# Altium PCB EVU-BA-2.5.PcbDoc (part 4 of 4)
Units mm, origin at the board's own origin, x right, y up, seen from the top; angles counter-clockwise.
Board outline 80 x 82.5 mm, 4 copper layers (Top Layer, Int1, Int2, Bottom Layer), stack 1.49 mm thick; 257 components, 201 nets, 889 pads, 696 vias.
Unrouted connection lines stored in the file: 1.
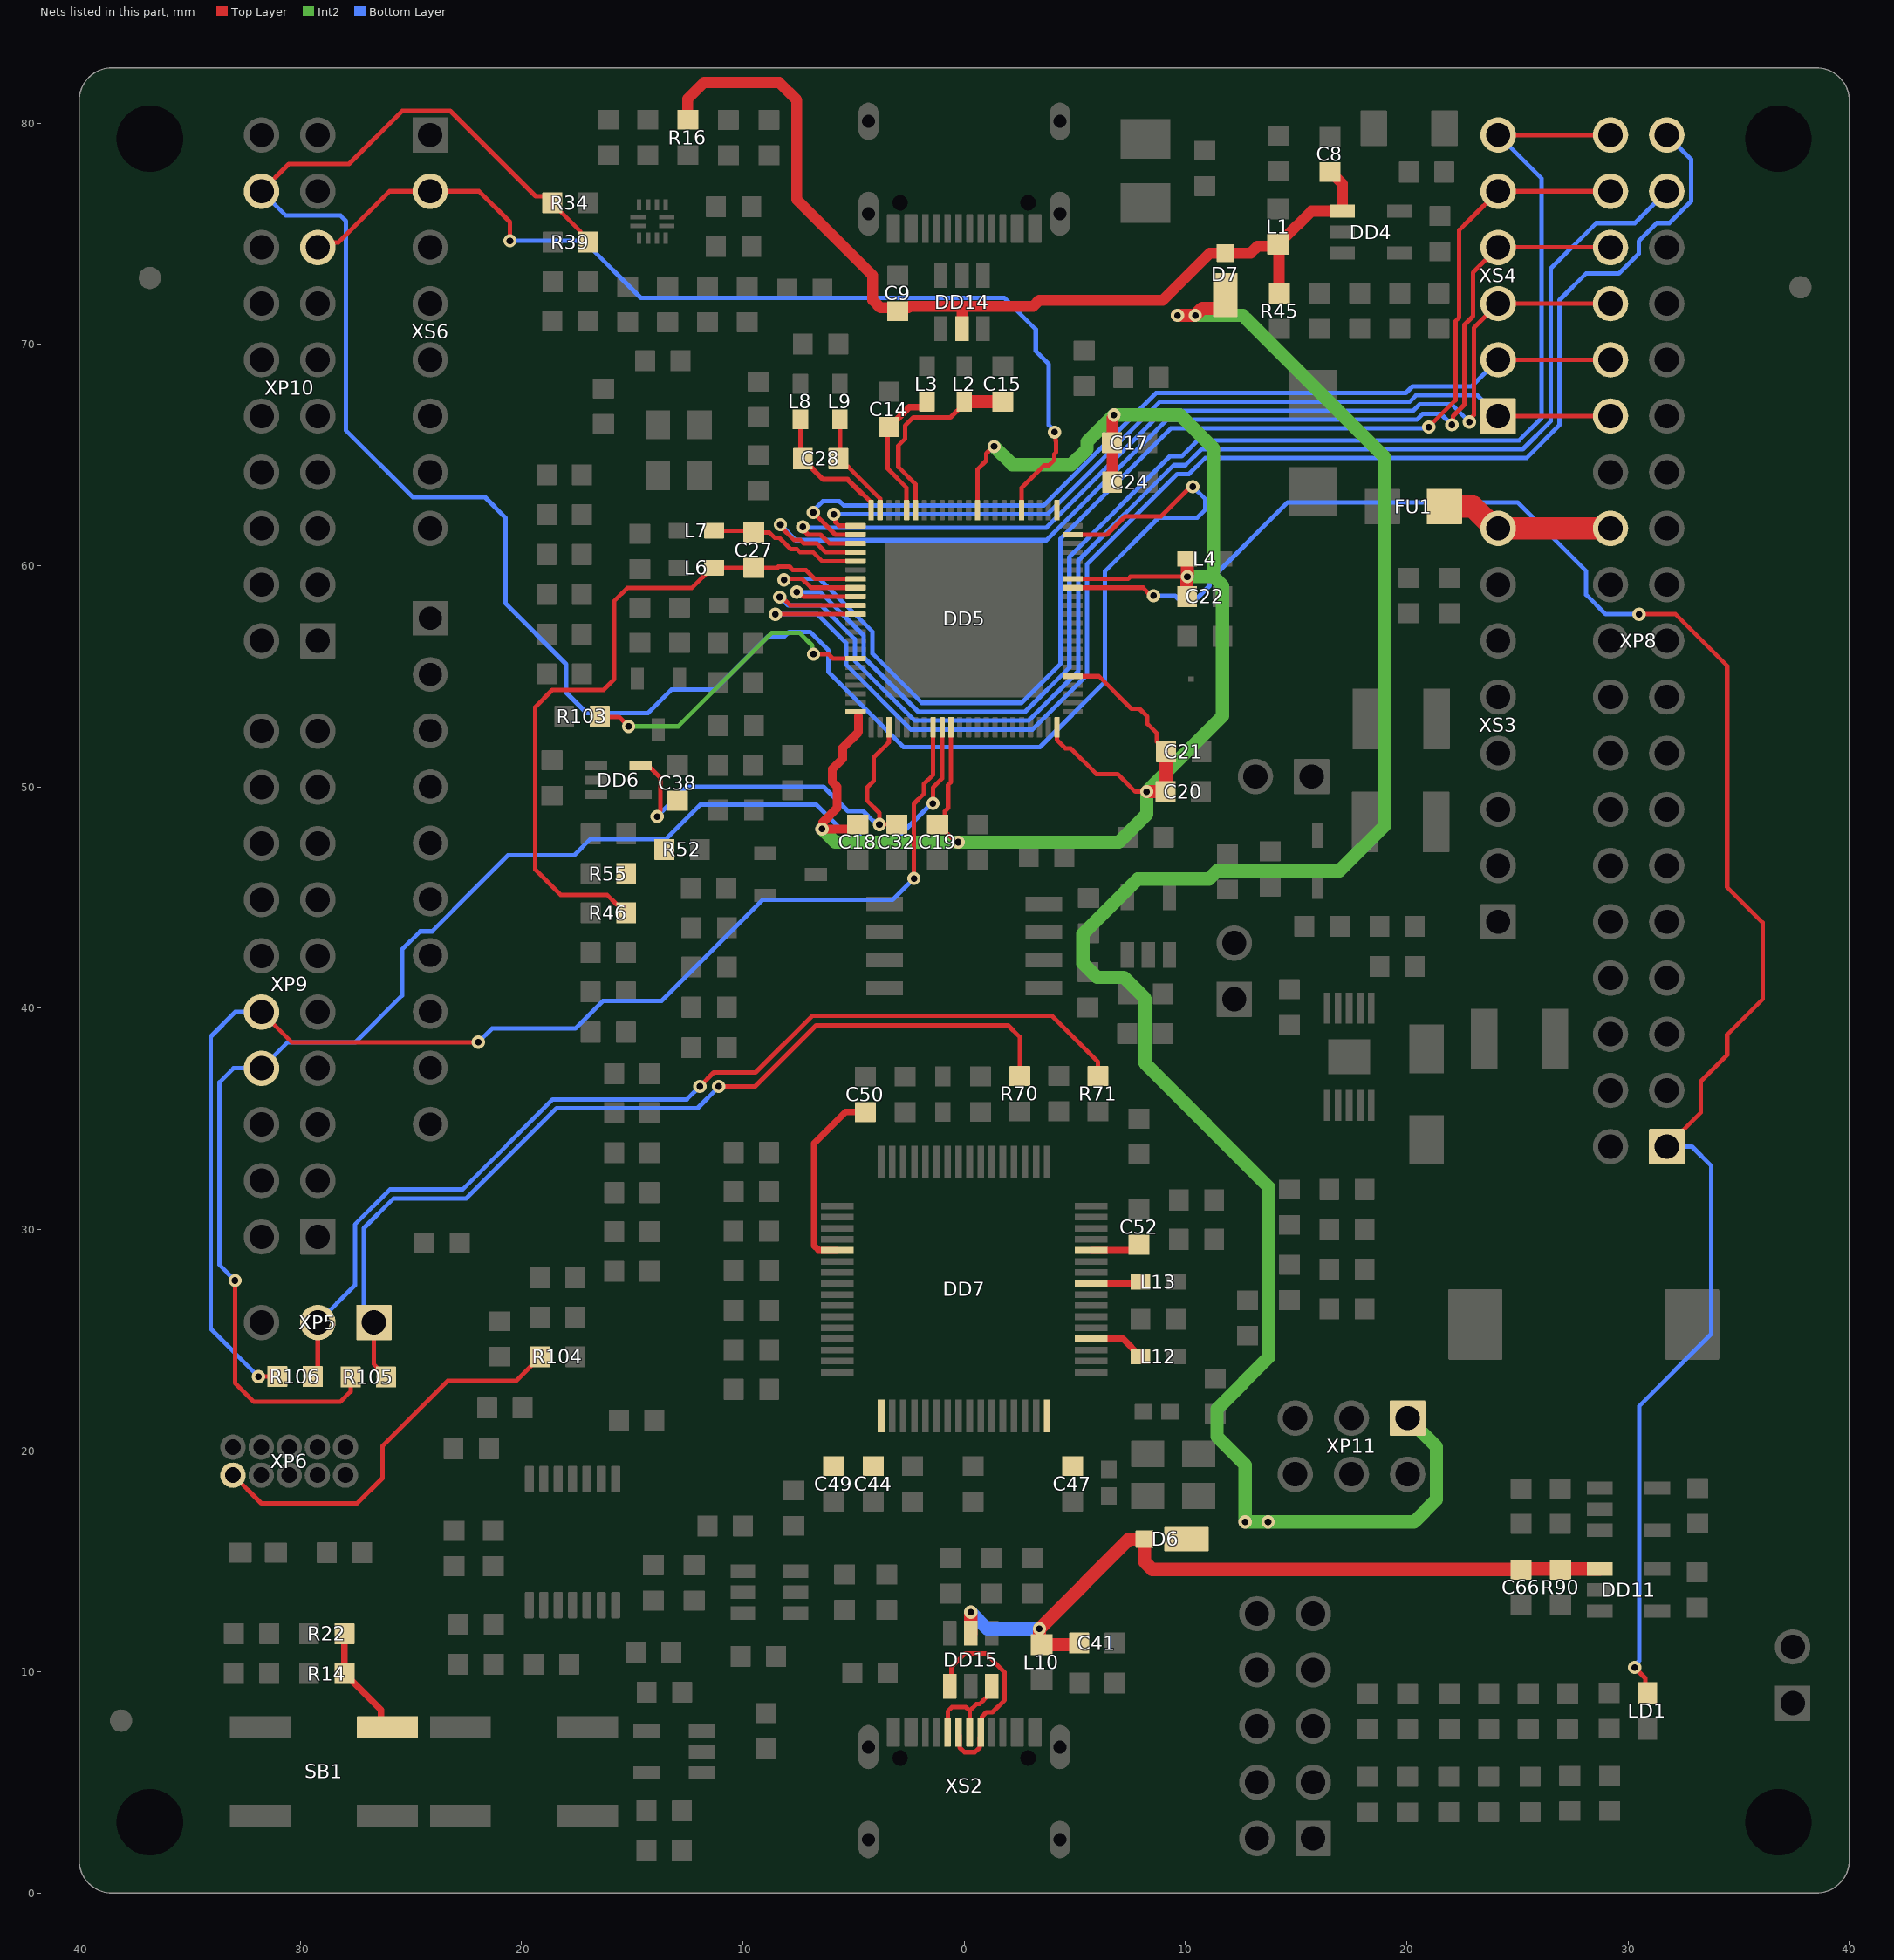
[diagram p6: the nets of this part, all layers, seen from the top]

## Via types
v1: diameter 0.6, hole 0.3, Top Layer to Bottom Layer, tented both sides, 670 vias
v2: diameter 0.6, hole 0.3, Top Layer to Bottom Layer, tented bottom, 26 vias

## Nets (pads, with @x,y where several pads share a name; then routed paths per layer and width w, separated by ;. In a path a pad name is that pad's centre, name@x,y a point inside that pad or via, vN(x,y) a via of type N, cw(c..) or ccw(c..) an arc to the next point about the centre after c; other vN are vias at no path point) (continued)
TST: DD5.38 R103.1 | length 14.1
  Top Layer w0.2: R103.1@-16.45,53.159 -15.592,53.159 v1(-15.167,52.734) ; v1(-6.807,55.999) -6.138,55.999 -5.938,55.8 DD5.38@-4.905,55.8
  Int2 w0.2: v1(-15.167,52.734) -12.922,52.734 -8.701,56.955 -7.428,56.955 -6.864,56.391 -6.864,56.056 v1(-6.807,55.999)
TUSB_INT/PB11: DD5.87 R34.2 R39.2 XP10.18 | length 99
  Top Layer w0.2: XP10.18@-31.75,76.92 -30.518,78.152 -27.798,78.152 -25.39,80.56 -23.229,80.56 -19.361,76.692 -18.909,76.692 R34.2@-18.61,76.393 -18.61,76.368 -17.347,75.105 -17.347,74.965 R39.2@-16.997,74.615 ; DD5.87@4.905,61.4 6.442,61.4 7.263,62.221 8.893,62.221 10.236,63.564 v1(10.336,63.564)
  Bottom Layer w0.2: XP10.18@-31.75,76.92 -30.65,75.82 -28.186,75.82 -27.93,75.564 -27.93,66.1 -24.918,63.087 -21.653,63.087 -20.722,62.156 -20.722,58.286 -17.979,55.543 -17.979,54.258 -17.054,53.334 -14.284,53.334 -13.223,54.395 -11.261,54.395 -8.856,56.8 -8.115,56.8 -7.915,57 -6.959,57 -6.139,56.18 -6.139,55.196 -2.738,51.795 3.42,51.795 6.355,54.73 6.355,59.731 8.79,62.166 10.534,62.166 10.9,62.532 10.9,63 v1(10.336,63.564)
TX_3/PB6: DD5.5 XP10.15 XS6.2 | length 45.9
  Top Layer w0.2: XP10.15@-29.21,74.38 -28.985,74.605 -28.279,74.605 -25.964,76.92 XS6.2@-24.13,76.92 -21.923,76.92 -20.528,75.525 v1(-20.528,74.676) ; DD5.5@2.6,62.505 2.6,63.275 2.6,63.518 3.62,64.538 3.841,64.538 4.082,64.778 4.082,65.041 4.153,65.113 4.153,65.61 4.131,65.633 4.131,65.983 v1(4.082,66.032)
  Bottom Layer w0.2: v1(-20.528,74.676) -17.19,74.676 -14.614,72.1 1.812,72.1 3.238,70.674 3.238,69.693 3.826,69.105 3.826,66.35 4.082,66.094 v1(4.082,66.032)
UART0_RX/PA7: DD5.52 R106.2 XP9.10 | length 60.2
  Top Layer w0.2: v1(-31.889,23.344) R106.2@-31.039,23.344 ; XP9.10@-31.75,39.82 -30.388,38.458 v1(-21.953,38.458) ; v1(-2.271,45.857) -2.276,45.863 -2.276,49.232 -1.809,49.699 -1.809,50.136 -1.4,50.545 -1.4,52.335 DD5.52@-1.4,52.695
  Bottom Layer w0.2: v1(-31.889,23.344) -34.05,25.505 -34.05,38.711 -32.941,39.82 XP9.10@-31.75,39.82 ; v1(-21.953,38.458) -21.328,39.083 -17.562,39.083 -16.321,40.325 -13.676,40.325 -9.112,44.89 -3.236,44.89 -2.271,45.855 v1(-2.271,45.857)
UART0_TX/PA6: DD5.53 R105.2 XP9.8 | length 64.2
  Top Layer w0.2: v1(-32.95,27.69) -32.95,23.055 -32.095,22.2 -28.198,22.2 -27.729,22.67 -27.729,23.324 R105.2@-27.725,23.328 ; v1(-1.409,49.25) -1.409,49.97 -1,50.379 DD5.53@-1,52.695
  Bottom Layer w0.2: v1(-32.95,27.69) -33.65,28.39 -33.65,36.649 -33.019,37.28 XP9.8@-31.75,37.28 -30.572,38.458 -27.507,38.458 -25.4,40.566 -25.4,42.648 -24.58,43.468 -24.045,43.468 -23.042,44.47 -23.042,44.482 -20.625,46.9 -17.629,46.9 -16.887,47.643 -13.473,47.643 -11.912,49.204 -6.685,49.204 -5.581,48.1 -5.044,48.1 -4.244,47.3 -3.416,47.3 -1.466,49.25 v1(-1.409,49.25)
UART_FTDI_RX: R71.2 R106.1 XP5.2 | length 46.7
  Top Layer w0.2: R106.1@-29.439,23.344 -29.21,23.574 XP5.2@-29.21,25.789 ; v1(-11.946,36.459) -11.319,37.087 -9.424,37.087 -6.859,39.652 3.964,39.652 6.05,37.566 R71.2@6.05,36.927
  Bottom Layer w0.2: XP5.2@-29.21,25.789 -27.53,27.469 -27.53,30.219 -25.949,31.8 -22.666,31.8 -18.591,35.875 -12.53,35.875 v1(-11.946,36.459)
UART_FTDI_TX: R70.2 R105.1 XP5.1 | length 42.6
  Top Layer w0.2: XP5.1@-26.67,25.789 -26.67,23.898 -26.125,23.353 R105.1@-26.125,23.328 ; v1(-11.096,36.459) -9.448,36.459 -6.684,39.223 1.984,39.223 2.51,38.696 R70.2@2.51,36.927
  Bottom Layer w0.2: XP5.1@-26.67,25.789 -27.13,26.249 -27.13,30.053 -25.783,31.4 -22.5,31.4 -18.425,35.475 -12.053,35.475 -11.096,36.433 v1(-11.096,36.459)
USB_5V_IN: D6.1 D7.1 XP11.1 | length 92.7
  Top Layer w0.6: v1(9.644,71.306) v1(10.444,71.306) 10.763,71.625 11.65,71.625 11.8,71.775 D7.1@11.8,72.225
  Int2 w0.2: 12.654,71.253 12.73,71.176
  Int2 w0.6: v1(9.644,71.306) 12.6,71.306 12.654,71.253 ; 12.73,71.176 18.998,64.908 18.998,48.239 16.969,46.21 11.44,46.21 11.06,45.83 7.837,45.83 5.368,43.361 5.368,42.023 6.007,41.383 7.222,41.383 8.171,40.434 8.171,37.504 13.777,31.898 13.777,24.233 11.425,21.881 11.425,20.627 12.7,19.351 v1(12.7,16.775) v1(13.734,16.775) 20.33,16.775 21.34,17.785 21.34,20.17 XP11.1@20.04,21.47
USB_N: DD15.3 XS2.A7 XS2.B7 | length 4.7
  Top Layer w0.2: XS2.B7@-0.75,7.27 -0.743,7.277 -0.743,8.22 -0.55,8.413 0.075,8.413 0.25,8.238 ; XS2.A7@0.25,7.27 0.25,8.238 ; DD15.3@1.245,9.35 1.245,9.095 0.85,8.7 0.85,8.695 0.694,8.54 0.552,8.54 0.25,8.238
USB_P: DD15.1 XS2.A6 XS2.B6 | length 9.5
  Top Layer w0.2: DD15.1@-0.595,9.395 -0.579,9.411 -0.579,10.21 0.051,10.84 0.964,10.84 1.823,9.981 1.823,8.719 1.274,8.17 1,8.17 0.8,7.97 0.8,7.225 XS2.B6@0.75,7.175 ; XS2.A6@-0.25,7.175 -0.2,7.125 -0.2,6.603 -0.2,6.58 0.01,6.37 0.49,6.37 0.7,6.58 0.7,7.025 XS2.B6@0.75,7.075
USER_BUT: R14.1 R22.1 SB1.2 | length 5.1
  Top Layer w0.3: R14.1@-28.001,9.922 R14.1@-28.001,9.897 ; R22.1@-28.001,11.722 R14.1@-28.001,9.897 ; SB1.2@-26.063,7.5 -26.353,7.79 -26.353,8.274 -27.676,9.597 -27.701,9.597 R14.1@-28.001,9.897
USER_LED/PC0: DD5.81 LD1.1 XP8.1 | length 87.5
  Top Layer w0.2: DD5.81@4.905,59 8.086,59 8.447,58.64 v1(8.555,58.64) ; v1(30.3,10.2) 30.785,9.715 30.785,9.12 LD1.1@30.872,9.033 ; v1(30.5,57.8) 32.15,57.8 34.48,55.47 34.48,45.462 36.08,43.862 36.08,40.395 34.48,38.795 34.48,37.879 33.28,36.679 33.28,35.27 XP8.1@31.75,33.74
  Bottom Layer w0.2: v1(8.555,58.64) 9.533,58.64 9.673,58.5 10.502,58.5 11.087,59.086 11.087,59.325 14.623,62.86 25.004,62.86 28.11,59.754 28.11,58.684 28.994,57.8 v1(30.5,57.8) ; v1(30.3,10.2) 30.3,10.308 30.5,10.508 30.5,22.006 33.762,25.268 33.762,30.185 33.767,30.19 33.767,32.863 32.891,33.74 XP8.1@31.75,33.74
VBUS_FTDI: C41.1 C66.2 D6.2 DD11.1 DD15.5 L10.2 R90.1 | length 35
  Top Layer w0.6: DD15.5@0.295,11.744 v1(0.295,12.7) ; L10.2@3.4,11.229 v1(3.4,11.946) 7.45,15.996 8.146,15.996 D6.2@8.15,16 8.15,14.976 8.501,14.625 C66.2@25.17,14.625 ; L10.2@3.5,11.229 5.129,11.229 C41.1@5.2,11.3 ; C66.2@25.17,14.65 26.95,14.65 DD11.1@28.725,14.65
  Bottom Layer w0.6: v1(0.295,12.7) 1.049,11.946 v1(3.4,11.946)
VBUS_MK_USB: C8.2 C9.1 D7.2 DD4.1 DD14.5 L1.2 R16.1 R45.1 | length 45.3
  Top Layer w0.5: R16.1@-12.491,80.152 -12.491,81.101 -11.756,81.836 -8.358,81.836 -7.561,81.039 -7.561,76.542 -4.131,73.112 -4.131,72.001 -3.78,71.65 -3.15,71.65 C9.1@-3,71.5 -2.85,71.65 -2.524,71.65 -2.453,71.721 -0.618,71.721 ; -0.568,71.721 3.122,71.721 3.395,71.994 8.977,71.994 11.109,74.125 D7.2@11.8,74.125 12.95,74.125 13.258,74.433 L1.2@14.108,74.433 ; DD14.5@-0.1,70.711 -0.1,71.671 ; R45.1@14.25,72.3 14.225,72.325 14.225,74.25 14.225,74.5 L1.2@14.2,74.525 14.225,74.525 14.45,74.75 14.45,74.775 15.7,76.025 DD4.1@17.082,76.025 17.082,77.259 16.556,77.785 C8.2@16.531,77.785
VCCA: C14.1 DD5.18 L3.2 | length 6.4
  Top Layer w0.2: C14.1@-3.1,66.562 C14.1@-3.4,66.262 -3.45,66.211 -3.45,64.368 -2.6,63.518 -2.6,62.865 DD5.18@-2.6,62.505 ; L3.2@-1.883,67.149 -1.683,67.349 L3.2@-1.683,67.412
  Top Layer w0.3: C14.1@-3.1,66.562 -3.075,66.562 -2.483,67.154 -1.883,67.154 L3.2@-1.883,67.149
VDD_PLL: C28.2 DD5.22 L8.2 | length 6.1
  Top Layer w0.2: L8.2@-7.4,66.612 -7.392,66.604 -7.392,64.913 C28.2@-7.289,64.81 ; -4.628,63.255 -4.6,63.255 -4.22,62.875 -4.22,62.525 DD5.22@-4.2,62.505
  Top Layer w0.24: C28.2@-7.289,64.81 -6.378,63.899 -5.272,63.899 -4.628,63.255
VDDA: C15.1 DD5.17 L2.2 | length 9.2
  Top Layer w0.2: DD5.17@-2.2,62.505 -2.2,63.582 -2.2,63.684 -2.974,64.458 -2.974,65.422 -2.675,65.721 -2.675,66.325 -2.296,66.704 -2.074,66.704 -2.069,66.699 -0.613,66.699 0,67.312 L2.2@0,67.412
  Top Layer w0.6: L2.2@0,67.412 C15.1@1.745,67.412
VDDIO: C17.1 C18.1 C19.1 C20.1 C21.1 C22.1 C24.1 DD5.1 DD5.10 DD5.44 DD5.54 DD5.66 DD5.71 DD5.82 L4.2 | length 87.9
  Top Layer w0.2: DD5.54@-0.6,52.695 -0.6,50.213 -0.725,50.088 -0.725,49.04 -0.864,48.9 -0.864,48.636 C19.1@-1.2,48.3 -1.175,48.3 -0.375,47.5 v1(-0.275,47.5) ; DD5.10@0.6,62.505 0.6,64.346 1,64.746 1,65.065 1.317,65.382 v1(1.353,65.382) ; DD5.66@4.2,52.695 4.2,52.109 4.574,51.735 4.818,51.735 5.972,50.582 6.931,50.582 7.733,49.78 v1(8.251,49.78) ; DD5.71@4.905,55 6.09,55 7.557,53.533 7.918,53.533 8.279,53.172 8.279,52.849 8.715,52.413 8.715,52.042 8.95,51.807 8.975,51.807 C21.1@9.113,51.669 ; DD5.82@4.905,59.4 7.413,59.4 7.513,59.5 v1(10.087,59.5) ; C24.1@6.686,63.745 C24.1@6.686,63.77 ; C20.1@9.101,49.78 C20.1@9.113,49.792
  Top Layer w0.4: v1(-6.423,48.093) -5.012,48.093 C18.1@-4.805,48.3 ; v1@-6.423,48.117 -6.384,48.155 -6.384,48.401 -5.741,49.044 -5.741,50.007 -5.957,50.222 -5.957,50.802 -5.495,51.263 -5.495,51.757 -4.77,52.482 -4.77,53.2
  Top Layer w0.5: C24.1@6.686,63.77 6.686,65.572 6.68,65.578 6.68,66.692 6.77,66.781 v1(6.77,66.808) ; v1@10.068,59.481 v1(10.087,59.5) v1@10.081,59.506 ; L4.2@10.075,60.3 L4.2@10.081,60.294
  Top Layer w0.6: v1(8.251,49.78) C20.1@9.101,49.78 ; C20.1@9.113,49.792 C21.1@9.113,51.669 ; C22.1@10.068,58.6 v1@10.068,59.481 ; v1@10.081,59.506 L4.2@10.081,60.294
  Int2 w0.6: v1(-6.423,48.093) -5.829,47.5 v1(-0.275,47.5) 6.993,47.5 8.251,48.757 v1(8.251,49.78) 11.675,53.204 11.675,59.088 11.262,59.5 ; v1(1.353,65.382) 2.174,64.562 4.848,64.562 5.553,65.267 5.553,65.592 v1(6.77,66.808) 9.756,66.808 11.262,65.302 11.262,59.5 ; v1(10.087,59.5) 11.262,59.5
VIN: FU1.1 XP8.24 XS3.8 | length 7.8
  Top Layer w1: FU1.1@21.802,62.66 22.995,62.66 23.975,61.68 XS3.8@24.13,61.68 XP8.24@29.21,61.68
VIN<0>: DD5.23 XP8.28 XS4.1 | length 39.1
  Top Layer w0.2: v1(-5.889,62.317) -5.813,62.241 -5.813,61.958 -5.655,61.8 DD5.23@-4.905,61.8 ; XS4.1@24.13,66.76 XP8.28@29.21,66.76
  Bottom Layer w0.2: v1(-5.889,62.317) 3.756,62.317 8.839,67.4 20.128,67.4 20.424,67.696 23.194,67.696 XS4.1@24.13,66.76
VIN<1>: DD5.24 XP8.30 XS4.2 | length 41.4
  Top Layer w0.2: v1(-6.82,62.4) -5.82,61.4 DD5.24@-4.905,61.4 ; XS4.2@24.13,69.3 XP8.30@29.21,69.3
  Bottom Layer w0.2: v1(-6.82,62.4) -6.82,62.485 -6.388,62.917 -5.641,62.917 -5.441,62.717 3.59,62.717 8.673,67.8 19.963,67.8 20.258,68.096 22.926,68.096 XS4.2@24.13,69.3
VIN<2>: DD5.25 XP8.32 XS4.3 | length 46.5
  Top Layer w0.2: v1(-7.289,61.75) -7.289,61.642 -7.08,61.433 -7.08,61.4 -6.489,61.4 -6.089,61 DD5.25@-4.905,61 ; v1(22.83,66.49) 22.83,66.598 23.03,66.798 23.03,70.74 XS4.3@24.13,71.84 XP8.32@29.21,71.84
  Bottom Layer w0.2: v1(-7.289,61.75) -7.256,61.717 3.722,61.717 9.004,67 20.294,67 20.59,67.296 22.024,67.296 v1(22.83,66.49)
VIN<3>: DD5.26 XP8.34 XS4.4 | length 51.1
  Top Layer w0.2: v1(-8.304,61.85) -8.304,61.773 -7.684,61.153 -7.399,61.153 -7.246,61 -6.655,61 -6.255,60.6 DD5.26@-4.905,60.6 ; v1(22.04,66.362) 22.09,66.412 22.09,66.76 22.6,67.27 22.6,70.876 23,71.276 23,73.25 XS4.4@24.13,74.38 XP8.34@29.21,74.38
  Bottom Layer w0.2: v1(-8.304,61.85) -7.604,61.15 3.72,61.15 9.17,66.6 20.46,66.6 20.72,66.86 21.542,66.86 v1(22.04,66.362)
VIN<4>: DD5.30 XP8.36 XS4.5 | length 61
  Top Layer w0.2: v1(-8.144,59.353) -8.097,59.4 -7.317,59.4 -6.917,59 DD5.30@-4.905,59 ; v1(20.998,66.26) 20.998,66.27 22.2,67.472 22.2,71.041 22.375,71.216 22.375,75.165 22.86,75.65 XS4.5@24.13,76.92 XP8.36@29.21,76.92
  Bottom Layer w0.2: v1(-8.144,59.353) -8.097,59.4 -6.531,59.4 -4.139,57.008 -4.139,56.025 -1.91,53.795 2.592,53.795 4.355,55.559 4.355,61.219 9.336,66.2 20.938,66.2 v1(20.998,66.26)
VIN<5>: DD5.31 XP8.38 XS4.6 | length 66.3
  Top Layer w0.2: v1(-7.566,58.8) -7.458,58.8 -7.258,58.6 DD5.31@-4.905,58.6 ; XS4.6@24.13,79.46 XP8.38@29.21,79.46
  Bottom Layer w0.2: v1(-7.566,58.8) -6.497,58.8 -4.539,56.843 -4.539,55.859 -2.075,53.395 2.757,53.395 4.755,55.393 4.755,60.394 9.301,64.94 9.835,64.94 10.478,65.583 ; 10.479,65.583 10.556,65.66 25.08,65.66 26.1,66.68 26.1,77.49 XS4.6@24.13,79.46
VIN<6>: DD5.32 XP8.35 | length 63.4
  Top Layer w0.2: v1(-8.334,58.576) -8.237,58.576 -7.861,58.2 DD5.32@-4.905,58.2
  Bottom Layer w0.2: v1(-8.334,58.576) -7.958,58.2 -6.462,58.2 -4.939,56.677 -4.939,55.694 -2.241,52.995 2.923,52.995 5.155,55.227 5.155,60.228 9.467,64.54 10.001,64.54 ; 10.002,64.54 10.722,65.26 25.246,65.26 26.5,66.514 26.5,67.08 26.5,73.418 28.562,75.48 30.31,75.48 XP8.35@31.75,76.92
VIN<7>: DD5.33 XP8.37 | length 67.6
  Top Layer w0.2: v1(-8.529,57.8) DD5.33@-4.905,57.8
  Bottom Layer w0.2: v1(-8.529,57.8) -6.628,57.8 -5.339,56.511 -5.339,55.528 -2.407,52.595 3.089,52.595 5.555,55.062 5.555,60.063 9.632,64.14 10.167,64.14 ; 10.168,64.14 10.887,64.86 25.411,64.86 26.9,66.349 26.9,66.473 26.9,72 28.095,73.195 29.581,73.195 30.48,74.094 30.48,74.666 31.294,75.48 31.866,75.48 32.85,76.464 32.85,78.36 XP8.37@31.75,79.46
VPHY: DD7.4 L12.1 | length 2.6
  Top Layer w0.3: DD7.4@5.738,25.05 7.17,25.05 L12.1@7.967,24.254
VPLL: DD7.9 L13.1 | length 2.2
  Top Layer w0.3: DD7.9@5.738,27.55 L13.1@7.933,27.55
VREF_1V: C32.2 C38.1 DD5.47 DD6.5 R52.2 R55.2 | length 20.1
  Top Layer w0.2: DD6.5@-14.625,50.95 -14.525,50.85 -14.171,50.85 -13.721,50.4 -13.721,48.92 -13.875,48.766 v1(-13.875,48.658) ; DD5.47@-3.4,52.695 -3.4,52.013 -3.43,51.983 -4.095,51.318 -4.095,50.259 -4.39,49.964 -4.39,49.379 -3.83,48.819 v1(-3.83,48.3) C32.2@-3.045,48.3
  Bottom Layer w0.2: v1(-13.875,48.658) -12.529,50.004 -6.354,50.004 -5.25,48.9 -4.564,48.9 -4.121,48.457 -4.095,48.457 -3.938,48.3 v1(-3.83,48.3)
VREFN: C27.1 DD5.27 L7.2 | length 7
  Top Layer w0.2: L7.2@-11.3,61.575 -9.575,61.575 C27.1@-9.5,61.5 -8.803,61.5 -8.553,61.25 -8.347,61.25 -7.85,60.753 -7.564,60.753 -7.411,60.6 -6.82,60.6 -6.42,60.2 DD5.27@-4.905,60.2
VREFP: C27.2 DD5.29 L6.2 R46.1 | length 31.5
  Top Layer w0.2: R46.1@-15.325,44.305 -15.325,44.33 -15.675,44.68 -15.7,44.68 -16.14,45.12 -18.24,45.12 -19.378,46.258 -19.378,53.613 -18.616,54.375 -16.298,54.375 -15.822,54.851 -15.822,58.391 -15.227,58.985 -12.315,58.985 L6.2@-11.4,59.9 ; L6.2@-11.3,59.9 C27.2@-9.5,59.9 -8.446,59.9 -8.393,59.953 -7.896,59.953 -7.743,59.8 -7.152,59.8 -6.752,59.4 DD5.29@-4.905,59.4
VREGOUT: C44.2 C47.1 C49.2 C50.1 C52.1 DD7.12 DD7.37 DD7.49 DD7.64 | length 10.9
  Top Layer w0.3: DD7.37@-5.738,29.05 -6.569,29.05 -6.776,29.257 -6.776,33.892 -5.366,35.302 C50.1@-4.465,35.302 ; DD7.12@5.738,29.05 7.65,29.05 C52.1@7.9,29.3
VSS_PLL: C28.1 DD5.21 L9.2 | length 5
  Top Layer w0.2: L9.2@-5.615,66.612 -5.615,64.909 C28.1@-5.689,64.835 -5.689,64.81 -5.339,64.46 -5.239,64.46 -3.8,63.021 DD5.21@-3.8,62.505
VTRef: R104.2 XP6.1 | length 18
  Top Layer w0.2: XP6.1@-33.039,18.888 -31.764,17.613 -27.431,17.613 -26.284,18.759 -26.284,20.206 -23.344,23.146 -20.248,23.146 -19.523,23.871 -19.521,23.871 -19.171,24.221 R104.2@-19.171,24.246
pads on no net: DD2.4 DD5.35 DD7.18 DD7.19 DD7.22 DD7.23 DD7.24 DD7.26 DD7.27 DD7.28 DD7.29 DD7.30 DD7.32 DD7.33 DD7.34 DD7.36 DD7.45 DD7.46 DD7.54 DD7.55 DD7.57 DD7.58 DD7.59 DD7.60 DD11.4 DD13.4 FM1.1 FM2.1 FM3.1 XP8.29 XP8.31 XS1. XS1.A8 XS1.B8 XS2. XS2.A8 XS2.B8 XS3.1

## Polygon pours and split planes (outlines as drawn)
VREF_1V on Top Layer "VREF_1V_L01_P010" (solid, pour order 10): -12.475,49.803 -12.475,48.262 -13.1,47.637 -13.093,47.63 -13.093,46.716 -14.209,45.6 -15.703,45.6 -15.725,45.623 -15.725,46.528 -15.703,46.55 -15.518,46.55 -14.15,47.917 -14.15,49.077 -13.425,49.803
GND on Top Layer "Top Layer-GND" (solid, pour order 83): 3.303,44.793 3.303,47.609 7.235,47.609 7.304,47.678 7.304,44.87 6.99,44.87 6.004,43.885 6.004,33.046 6.187,32.864 6.187,31.62 7.354,30.452 8.779,30.452 8.779,31.877 9.104,32.202 10.379,32.202 10.817,31.765 10.817,27.109 cw(c10.052,27.179) 9.982,26.415 9.567,26.415 9.139,26.415 9.139,25.465 11.3,25.465 11.909,26.342 13.255,26.344 13.359,26.449 13.359,36.651 13.705,36.997 33.097,36.997 33.097,20.302 39.929,20.302 39.929,82.497 -40.071,82.497 -40.071,0.002 39.092,0.002 39.929,0.908 39.929,20.302 29.674,20.302 21.2,13.833 17.734,13.833 17.742,9.944 12.629,9.944 12.629,15.177 6.773,15.177 6.773,8.413 2.829,8.413 2.829,5.434 -2.971,5.434 -2.971,8.413 -1.476,9.908 -1.476,12.37 -8.454,12.375 -8.454,9.944 -8.571,9.802 -11.08,9.802 -11.08,14.461 -12.471,15.852 -12.471,17.602 -23.122,17.602 -33.793,17.602 -33.793,48.02 -20.131,61.682 -17.6,61.682 -17.6,54.754 -20.293,54.754 -20.598,54.448 -20.598,48.678 -16.714,44.793
VREGOUT on Top Layer "Top Layer-VREGOUT" (solid, remove dead copper, pour order 14): 5.375,26.05 3.651,26.05 3.651,23.823 4.447,23.027 5.065,23.027 5.375,22.716 5.375,18.9 4.425,18.9 4.425,19.85 3.6,20.675 3.6,21.4 3.438,21.562 -3.625,21.562 -3.625,18.95 -3.675,18.9 -6.375,18.9 -6.375,22.019 -6.094,22.3 -5.697,22.3 -5.4,22.597 -5.4,29.2 5.375,29.2
GND on Top Layer "NONET_L01_P-001" (solid, remove dead copper, pour order 62): 6.954,24.921 6.947,19.096 6.601,18.75 6.125,18.75 5.375,19.5 5.375,23.027 4.447,23.027 3.651,23.823 3.651,26.05 5.826,26.05
GND on Top Layer "Top Layer-GND 1" (solid, remove dead copper, pour order 75): -34.444,47.386 -34.444,24.299 -25.67,24.299 -25.67,17.102 -10.428,17.102 -10.428,16.121 -9.9,16.121 -9.9,16.096 -8.2,16.096 -7.855,15.751 -7.855,14.4 -7,14.4 -6.7,14.1 -4.9,14.1 -4.9,15.788 -3.684,15.788 -1.058,15.751 0.875,17.272 0.875,18.1 -6.375,18.1 -6.952,19.056 -6.952,22.521 -6.681,22.521 -6.489,22.713 -6.476,22.7 -6.476,23.7 -5.001,23.7 -5,24.55 -7.213,24.55 -9.369,22.394 -16.425,29.45 -16.425,39.229 -28.396,51.2 -30.63,51.2
GND on Top Layer "NONET_L01_P-001" (solid, remove dead copper, pour order 73): -9.995,35.839 -6.384,39.45 1.068,39.45 1.975,38.543 1.975,36.38 -3.648,36.38 -3.727,36.301 -3.727,34.845 -3.704,34.822 -4.479,34.047 -4.479,32.75 3.5,32.75 5.296,30.954 5.296,29.45 -5.479,29.45 -5.479,31.45 -7.132,31.45 -7.254,31.327 -7.254,30.45 -8.182,30.45 -8.604,30.872 -8.604,32.902 -8.607,32.902 -10.132,34.427 -13.216,34.427 -13.216,35.429 -12.806,35.839
FTDI_VCCIO on Top Layer "NONET_L01_P-001" (solid, remove dead copper, pour order 40): -3.125,35.741 1.249,35.741 2.4,34.591 2.4,33.038 -3.4,33.038 -3.4,35.466
5V_INT on Top Layer "5V_INT_L01_P036" (solid, remove dead copper, pour order 36): 13.825,20.47 13.825,24.46 13.825,26.828 14.225,27.228 15.15,27.228 15.15,25.973 15.623,25.5 17.382,25.5 17.65,25.768 17.65,26.85 20.35,26.85 20.9,26.3 20.9,24.2 21.7,23.4 25.5,23.4 26.1,24 26.1,40.2 27.9,40.2 27.9,32.085 28.61,31.375 33.15,31.375 34.375,30.15 34.375,23.35 33.125,22.1 20.902,22.1 19.602,23.4 15.9,23.4 15.9,20.47
5V on Top Layer "5V_L01_P034" (solid, pour order 34): 26.7,16.758 13.917,16.758 13.917,20.2 25.8,20.2 28.477,20.2 29.3,19.377 29.3,18 28.15,18
5V on Top Layer "NONET_L01_P-001" (solid, remove dead copper, pour order 33): 21.099,77.31 21.086,77.323 21.086,80.566 23,80.566 23,77.317
3V3_QSPI on Top Layer "NONET_L01_P-001" (solid, remove dead copper, pour order 20): 3.724,46.928 3.724,44.38 5.88,44.38 6.073,44.573 6.073,46.812 5.61,47.275 4.071,47.275
3V3_FTDI on Top Layer "3V3_FTDI_L01_P024" (solid, remove dead copper, pour order 24): 30.75,16.1 30.779,16.071 33.829,16.071 34.735,15.165 34.735,14.057 32.678,14.057 32.671,14.05 32.371,14.35 30.75,14.35
NetC68_2 on Top Layer "NETC68_2_L01_P035" (solid, remove dead copper, pour order 35): 18.3,36.3 18.3,33.276 21.9,29.676 21.9,24.4 24.325,24.4 24.325,33.628 22.472,35.15 20.15,35.15 19,36.3
GND on Top Layer "GND_L01_P039" (solid, remove dead copper, pour order 39): 17.8,32.275 17.8,27.75 17.85,27.7 21,27.7 21,29.675 18.4,32.275
LDO_OUT_1P1 on Int2 "LDO_OUT_1P1_L03_P078" (solid, pour order 78): -7.044,69.389 -7.8,69.389 -7.8,55.999 -8.965,55.999 -9.045,55.919 -9.045,55.311 -8.883,55.149 -7.885,55.149 -7.376,54.64 -7.376,51.369 -3.573,47.809 7.216,47.72 11.577,53.102 11.772,64.641 7.875,68.301 1.237,68.301 1.237,69.104 1.002,69.339 0.183,69.339 -0.055,69.101 -0.055,68.565 -7.044,68.633
3V3_FTDI on Int2 "3V3_FTDI_L03_P077" (solid, remove dead copper, pour order 77): 8.473,37.202 13.777,31.898 13.777,24.203 16.51,21.47 24.68,21.47 29.884,16.266 33.684,16.266 34.9,15.05 34.9,14.1 34.4,13.6 14.9,13.6 10.35,13.486 -7.111,13.486 -14.85,21.225 -14.85,24.095 -1.564,37.632 -1.573,38.101 -1.256,38.425 -0.445,38.425 7.25,38.425
3V3 on Int2 "3V3_L03_P079" (solid, pour order 79): -40,82.5 -40,0 40,0 40,82.5
GND on Bottom Layer "Bottom Layer-GND" (solid, remove dead copper, pour order 74): 7.883,49.959 7.883,50.079 6.779,51.182 5.913,51.182 5.913,48.633 5.098,47.818 -4.676,47.818 -5.877,49.019 -12.187,49.019 -13.837,47.369 -21.932,47.369 -24.312,44.989 -24.312,60.448 -23.286,61.473 -20.43,58.617 -18.341,56.528 -18.341,54.531 -17.179,53.369 -14.975,53.369 -13.481,54.864 -11.439,54.864 -8.541,57.761 -8.541,58.001 -12.112,58.001 -12.112,59.969 -9.312,62.769 -9.312,66.919 -8.793,67.438 3.876,67.438 2.7,67.438 2.7,82.569 -40.012,82.569 -40.012,0.069 39.988,0.069 39.988,82.569 -8.012,82.569 2.7,82.569 2.7,67.448 19.389,67.308 20.246,68.165 22.914,68.165 24.118,69.369 24.118,79.529 31.738,79.529 31.738,57.869 28.538,57.869 25.949,60.458 22.971,60.478 20.94,62.944 14.62,62.944 10.904,59.228 10.863,55.409 27.148,55.409 30.401,55.409 31.738,54.072 31.738,43.051 31.126,42.439 28.849,42.439 28.047,41.637 28.047,41.429 27.044,40.427 21.854,40.427 17.539,44.989 17.539,48.733 16.314,49.959
GND on Bottom Layer "GND_L04_P086" (solid, pour order 86): -23.407,51.088 -23.407,48.314 -23.193,48.1 -18.126,48.1 -17.104,49.123 -17.178,49.197 -17.178,49.523 -21.843,49.523
GND on Bottom Layer "GND_L04_P084" (solid, pour order 84): -21.39,51.65 -16.088,51.65 -15,50.562 -15.475,50.087 -15.475,49.923 -21.513,49.923 -23.573,51.983 -22.915,51.325 -22.915,53.144 -21.68,51.909
3V3 on Bottom Layer "NONET_L01_P-001" (solid, remove dead copper, pour order 57): -12.1,57.931 -9.061,57.931 -9.029,57.899 -8.991,57.938 -8.991,60.391 -7.496,60.391 -5.531,62.356 3.888,62.356 7.325,65.792 7.325,66.451 6.455,66.451 4.999,64.995 -0.094,64.995 -1.651,63.438 -2.519,63.438 -2.882,63.8 -8.2,63.8 -12.1,59.9
GND on Bottom Layer "NONET_L01_P-001" (solid, remove dead copper, pour order 56): 4.386,61.156 -7.687,61.156 -7.838,61.006 -7.838,59.4 -6.531,59.4 -4.139,57.008 -4.139,55.721 -2.213,53.795 2.592,53.795 4.353,55.557 4.353,55.563
GND on Int1 "GND_L02_P000" (solid, pour order 0): -40.199,82.404 -40.199,-0.096 39.801,-0.096 39.801,82.404

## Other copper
Top Layer:
  pour cut-out: -5.131,36.452 -5.131,35.741 2.96,35.741 2.96,36.452
  pour cut-out: -17.407,77.164 -21.925,77.164 -21.925,74.437 -21.939,74.423 -17.749,70.233 -13.949,70.233 -13.949,68.68 -17.178,68.68 -17.178,65.593 -13.403,65.593 -13.403,63.243 -11.039,63.243 -10.403,63.942 -10.411,65.261 -10.778,65.628 -10.778,67.243 -8.836,67.243 -8.836,63.374 -9.517,62.418 -11.557,62.418 -12.027,61.948 -12.027,57.632 -10.366,57.632 -10.31,48.118 -8.31,47.443 -8.31,48.644 -8.31,50.298 -7.08,50.298 -6.709,49.927 -6.709,47.634 -6.465,47.634 -6.287,47.443 1.669,47.443 1.669,47.559 1.873,47.763 9.902,47.763 10.496,47.763 10.496,55.618 11.245,56.368 11.245,59.775 12.688,59.79 12.688,63.078 14.494,63.103 14.494,58.692 18.81,54.377 18.81,49.427 18.81,47.1 18.259,46.549 11.464,46.549 11.183,46.269 11.183,39.678 12.223,38.638 19.467,38.638 20.202,39.373 20.202,40.12 21.12,41.038 21.12,42.84 20.861,43.1 20.125,43.1 19.915,43.31 19.915,44.19 20.088,44.363 23.428,44.363 23.519,44.454 23.583,53.1 23.531,59.983 30.008,59.983 30.882,60.858 30.882,62.588 29.274,64.196 12.597,64.196 12.597,69.649 24.181,69.649 24.069,76.963 19.7,76.963 18.81,76.073 18.81,75.563 18.569,75.322 18.569,74.788 17.309,74.788 17.309,78.696 16.964,79.04 11.898,79.04 11.344,78.486 6.686,78.486 5.801,77.601 5.801,71.078 9.362,71.078 10.997,69.443 10.997,63.422 7.864,63.422 7.839,63.397 7.828,63.408 7.828,66.049 7.962,66.049 8.364,66.45 8.364,69.418 5.892,69.418 5.801,69.327 4.319,69.327 3.596,68.604 1.462,68.604 1.152,68.915 1.152,71.743 2.302,71.743 2.302,76.963 -2.829,76.963 -3.303,76.489 -3.303,75.538 -3.172,75.538 -2.339,74.704 -2.339,72.343 -4.528,72.343 -4.528,67.804 -5.783,67.804 -6.135,68.157 -6.135,70.548 -6.267,70.68 -6.338,73.143 -10.418,73.143 -10.418,81.438 -15.267,81.438 -15.267,79.89 -17.407,79.89
  pour cut-out: -25.117,60.412 -24.229,60.412 -24.229,58.329 -26.46,58.329
  pour cut-out: 27.297,46.629 28.184,46.629 28.184,46.126 28.13,46.072 27.297,46.072
  pour cut-out: 14.494,66.508 14.688,66.508 17.044,66.508 17.044,64.196 14.494,64.196
  pour cut-out: -13.263,54.281 -13.263,52.379 -12.371,51.984 -12.371,54.33 -13.214,54.33
  pour cut-out: -14.596,12.62 -14.596,11.353 -11.725,11.353 -11.725,12.62
  pour cut-out: -18.383,10.375 -18.383,8 -14.846,8 -14.846,10.375
  pour cut-out: -33.642,12.175 -33.642,8 -27.273,8 -27.273,12.175
  pour cut-out: -32.56,12.378 -32.56,11.656 -29.023,11.656 -29.023,12.378
  pour cut-out: -10.614,23.153 -10.614,22.12 -5.553,22.12 -5.221,23.153
  pour cut-out: 20.951,16.675 20.951,15.216 24.702,15.216 24.702,16.675
  pour cut-out: 24.545,15.262 24.545,13.466 27.896,13.466 27.896,15.262
  pour cut-out: 24.491,17.84 24.491,17.118 27.896,17.118 27.896,17.84
  pour cut-out: 6.214,34.554 6.214,34.058 13.359,34.058 13.359,34.554
  pour cut-out: -11.813,34.378 -11.813,33.882 -6.776,33.882 -6.776,34.378
  pour cut-out: -12.45,8.212 -13.348,8.212 -13.348,4.396 -12.45,4.396
  pour cut-out: -21.697,12.827 -23.59,12.827 -23.59,9.722 -21.697,9.722
  pour cut-out: -15.425,15.355 -14.521,17.602 -19.797,16.416 -20.643,14.767
  region net 3V3_FTDI: 9.117,24.765 9.117,23.904 10.206,22.815 12.053,22.815 13.274,24.036 13.274,25.642 12.347,25.642 11.47,24.765
  pour cut-out: -10.19,77.886 -10.19,81.321 -10.298,81.429 -10.29,81.438 -7.96,81.438 -7.96,78.995 -8.371,77.886
  pour cut-out: -15.706,61.008 -12.238,61.008 -12.027,60.796 -12.027,60.656 -12.45,60.233 -12.48,60.263 -15.706,60.263
  pour cut-out: -16.822,64.553 -16.822,59.85 -15.996,59.85 -15.706,60.14 -15.706,64.279 -15.974,64.548
  pour cut-out: -15.803,52.525 -13.597,52.525 -12.497,51.425
  region net GND: 9.849,17.738 9.849,17.96 9.849,18.55 11.872,18.55 12.221,18.201 12.221,17.094 12.08,16.977 9.849,16.977 9.849,17.359
  pour cut-out: -19.072,50.518 -19.078,50.513 -19.078,50.05 -18.172,50.05 -18.341,50.219 -18.341,50.4
  region net 3V3: -17.375,52.102 -18.625,52.102 -19.078,51.649 -19.078,50.751 -18.499,50.75 -17.853,50.102 -17.853,49.704 -17.598,49.45 -16.125,49.45 -16.125,49.85 -17.245,49.85 -17.375,49.98 -17.375,51.725
  pour cut-out: 31.437,9.679 31.218,9.859 16.944,9.859 16.944,2.809 30.14,2.809 31.437,4.107
  pour cut-out: -3.875,9.319 -3.875,10.41 -4.022,10.557 -4.491,10.557 -4.675,10.373 -4.675,9.319
  pour cut-out: -7.345,15.788 -7.345,15.292 -2.011,15.292 -2.011,15.788
  pour cut-out: -13.205,2.562 -13.701,2.562 -13.701,1.312 -13.205,1.312
  pour cut-out: -12.13,2.412 -12.13,2.908 -13.38,2.908 -13.38,2.412
  pour cut-out: -8.33,6.987 -8.33,7.687 -9.58,7.687 -9.58,6.987
  pour cut-out: -20.051,10.822 -20.051,12.827 -21.876,12.827 -21.876,10.822
  pour cut-out: -27.651,16.012 -28.147,16.012 -28.147,14.762 -27.651,14.762
  pour cut-out: -18.23,27.353 -16.976,27.353 -16.976,26.651 -18.23,26.651
  pour cut-out: 7.879,41.83 7.882,41.827 8.769,41.827 8.769,41.325 8.715,41.27 7.879,41.27
  pour cut-out: -13.403,50.525 -13.403,49.825 -12.497,49.825 -12.524,49.852 -12.524,50.574 -13.353,50.574
  region net VDDIO: -5.112,53.4 -4.527,53.4 -4.527,52.447 -5.112,51.863
  region net VDDIO: 4.2,62.935 4.2,62.2 5.995,62.2 7.136,63.341 7.136,64.222 7.114,64.245 6.259,64.245 6.252,64.238 4.949,62.935
  region net USB_5V_IN: 9.077,16.55 12.013,16.55 12.557,17.094 13.926,17.094 14.16,16.86 14.16,16.444 13.166,15.45 9.077,15.45 9.05,15.478 9.058,15.486 9.058,16.542
  region net 3V3: 30.75,18.75 32.697,18.75 34.435,18.75 34.585,18.6 34.735,18.449 34.735,17.291 34.494,17.05 34.188,17.05 34.025,17.213 34.025,17.519 33.694,17.85 32.697,17.85 30.75,17.85
  region net GND: 9.67,22.12 12.353,22.12 12.422,22.05 12.638,21.835 12.638,21.368 12.42,21.15 10.182,21.15 8.898,21.4 8.898,22.12
  region net 3V3_FTDI: 9.1,31.628 9.1,28.908 9.1,27.2 10.128,27.2 10.128,29.075 10.15,29.098 10.15,31.778 10.128,31.8 9.272,31.8
  region net 5V: 6.048,41.176 6.702,41.83 7.675,41.83 7.675,42.98 6.525,42.98 5.622,42.076 5.143,42.076 5.121,42.054 5.121,41.199 5.143,41.176
  region net 3V3: -18.147,75.068 -18.169,75.09 -19.024,75.09 -19.047,75.068 -19.046,75.066 -19.046,72.377 -19.023,72.355 -18.168,72.355 -18.146,72.377 -18.147,72.379
  region net 3V3: -22.007,22.371 -22.007,16.204 -21.734,15.932 -20.761,15.932 -19.461,17.231 -19.461,19.252 -19.447,19.267 -20.75,20.57 -20.75,22.028 -21.122,22.4 -21.978,22.4
  region net 3V3: -13.586,75.052 -13.586,74.111 -11.625,72.15 -11.125,72.15 -11.125,73.05 -11.285,73.05 -13.286,75.052
  region net 3V3: -16.839,68.45 -16.839,67.481 -13.222,67.481 -12.5,66.759 -12.5,65.71 -11.4,65.71 -11.4,68.018 -12.372,68.99 -12.372,70.874 -12.925,71.428 -13.875,71.428 -13.875,70.573 -13.265,69.963 -13.265,68.45
  region net 3V3: -14.992,6.493 -14.992,1.5 -14.777,1.285 -13.956,1.285 -13.75,1.491 -13.75,1.553 -13.75,4.135 -13.75,6.506 -14.04,6.796 -14.69,6.796
  pour cut-out: -8.069,16.9 -7.038,16.9 -7.038,17.523 -7.265,17.75 -8.065,17.75 -8.325,17.49 -8.325,17.156
  pour cut-out: -21.658,24.796 -20.132,24.796 -20.132,25.396 -21.658,25.396
  pour cut-out: -16.067,13.602 -16.067,11.576 -19.832,11.576 -19.832,13.602
  pour cut-out: -15.547,19.997 -15.547,18.167 -19.847,18.112 -19.847,19.997
  pour cut-out: -15.225,50.625 -15.225,49.95 -13.75,49.95 -13.75,50.525 -13.85,50.625
  pour cut-out: -16.25,48.375 -16.25,47.47 -16.477,47.243 -18.941,47.243 -18.941,46.802 -16.477,46.802 -16.25,46.575 -16.25,45.67 -15.959,45.67 -15.959,46.575 -15.732,46.802 -15.026,46.802 -14.877,46.952 -14.877,47.099 -15.021,47.243 -15.732,47.243 -15.959,47.47 -15.959,48.37
  pour cut-out: -18.217,64.553 -18.217,63.648 -18.444,63.421 -19.299,63.421 -19.299,62.979 -18.444,62.979 -18.217,62.753 -18.217,61.848 -17.926,61.848 -17.926,62.753 -17.699,62.979 -16.844,62.979 -16.844,63.421 -17.699,63.421 -17.926,63.648 -17.926,64.548
  pour cut-out: -31.845,74.285 -31.804,74.326 -31.845,74.367
Int2:
  pour cut-out: 7.89,45.443 11.43,45.443 9.019,42.905 5.69,42.905
  pour cut-out: 14.574,22.1 20.04,22.1 20.04,18.93 14.574,18.93
  pour cut-out: 12.7,18.93 20.04,18.93 20.088,18.978 21.34,18.978 21.34,17.785 20.33,16.775 13.108,16.775 12.7,17.183
Bottom Layer:
  pour cut-out: -3.543,77.424 -0.199,77.424 -0.199,75.361 -1.36,74.2 -3.515,74.2

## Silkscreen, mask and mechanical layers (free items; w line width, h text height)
Top Overlay:
  drawing of 55 lines, arcs and shapes, not listed
  text "VIN7" at 31.028,81.209 h1.5
  text "GND" at -33.143,81.135 h1.5
  text "VIN5" at 25.472,79.471 h1.5 r315
  text "PB3" at -27.041,78.871 h1.5 r45
  text "VIN6" at 33.412,76.951 h1.5 r315
  text "VIN4" at 25.461,76.92 h1.5 r315
  text "MCU" at -5.101,76.479 h2.5 r90
  text "USB" at 6.407,76.479 h2.5 r90
  text "PB7" at -27.033,76.325 h1.5 r45
  text "PB11" at -34.858,75.093 h1.5 r45
  text "GND" at 33.418,74.441 h1.5 r315
  text "VIN3" at 25.472,74.391 h1.5 r315
  text "PB6" at -27.044,73.791 h1.5 r45
  text "PB10" at -34.991,72.564 h1.5 r45
  text "NC" at 33.412,71.871 h1.5 r315
  text "VIN2" at 25.461,71.84 h1.5 r315
  text "PB8" at -27.044,71.251 h1.5 r45
  text "PB9" at -34.509,70.024 h1.5 r45
  text "NC" at 33.412,69.331 h1.5 r315
  text "VIN1" at 25.461,69.3 h1.5 r315
  text "PB15" at -27.376,68.711 h1.5 r45
  text "GND" at -34.773,67.432 h1.5 r45
  text "GND" at 33.418,66.821 h1.5 r315
  text "VIN0" at 25.472,66.771 h1.5 r315
  text "PB14" at -27.375,66.16 h1.5 r45
  text "3V3" at -34.466,64.872 h1.5 r45
  text "PC15" at 33.412,64.251 h1.5 r315
  text "RST_ALL" at 23.02,63.747 h1.5
  text "PB13" at -27.376,63.631 h1.5 r45
  text "PB5" at -34.488,62.404 h1.5 r45
  text "VIN" at 25.504,61.784 h1.5 r315
  text "PC14" at 33.412,61.711 h1.5 r315
  text "PB12" at -27.365,61.08 h1.5 r45
  text "PB4" at -34.511,59.853 h1.5 r45
  text "GND" at 25.478,59.181 h1.5 r315
  text "PC13" at 33.412,59.171 h1.5 r315
  text "PB2" at -27.058,58.54 h1.5 r45
  text "GND" at -34.773,57.272 h1.5 r45
  text "GND" at 33.418,56.661 h1.5 r315
  text "GND" at 25.478,56.641 h1.5 r315
  text "PB0" at -27.044,56.011 h1.5 r45
  text "PB1" at -34.702,54.773 h1.5 r45
  text "5V" at 25.634,54.143 h1.5 r315
  text "PC12" at 33.412,54.091 h1.5 r315
  text "PA13" at -27.082,51.831 h1.5 r45
  text "3V3" at 25.486,51.581 h1.5 r315
  text "PC11" at 33.412,51.551 h1.5 r315
  text "GND" at -35.013,50.779 h1.5 r45
  text "PA8" at -27.044,49.291 h1.5 r45
  text "PC10" at 33.412,49.011 h1.5 r315
  text "RSTU" at 25.472,48.991 h1.5 r315
  text "PA12" at -35.235,48.28 h1.5 r45
  text "PA10" at -27.111,46.751 h1.5 r45
  text "3V3" at 25.486,46.501 h1.5 r315
  text "PC9" at 33.412,46.471 h1.5 r315
  text "PA15" at -35.242,45.751 h1.5 r45
  text "PA11" at -27.08,44.2 h1.5 r45
  text "PC7" at 33.412,43.931 h1.5 r315
  text "PC8" at 25.472,43.911 h1.5 r315
  text "PA14" at -35.266,43.2 h1.5 r45
  text "GND" at 25.717,41.833 h1.5 r315
  text "PA9" at -27.044,41.671 h1.5 r45
  text "PC6" at 33.412,41.391 h1.5 r315
  text "GND" at -35.013,40.619 h1.5 r45
  text "GND" at -27.054,39.067 h1.5 r45
  text "PC4" at 33.412,38.851 h1.5 r315
  text "PA7" at -34.762,38.12 h1.5 r45
  text "AREF" at -27.081,36.548 h1.5 r45
  text "PC2" at 33.412,36.311 h1.5 r315
  text "PC5" at 24.665,35.687 h1.5
  text "PA6" at -34.787,35.591 h1.5 r45
  text "PC3" at 24.665,34.292 h1.5
  text "PA5" at -27.044,34.051 h1.5 r45
  text "PC0" at 33.412,33.771 h1.5 r315
  text "PA3" at -34.756,33.051 h1.5 r45
  text "PC1" at 24.665,32.901 h1.5
  text "PA4" at -27.033,31.5 h1.5 r45
  text "PA2" at -34.754,30.5 h1.5 r45
  text "PA0" at -27.03,28.971 h1.5 r45
  text "PA1" at -34.725,27.96 h1.5 r45
  text "UART0" at -22.671,21.1 h3 r90
  text "VIN" at 12.948,16.319 h1.8
  text "EXT5V" at 15.675,16.331 h1.8
  text "USB" at 19.955,16.331 h1.8
  text "JTAG" at -24.515,15.872 h3 r90
  text "PWR SEL" at 13.3,14.325 h3
  text "GND" at 38.343,12.785 h3 r90
  text "PWR" at -33.996,12.747 h3
  text "M0" at 8.388,11.83 h3
  text "M1" at 8.438,9.29 h3
  text "M2" at 8.422,6.75 h3
  text "USER" at 33.925,5.224 h3 r90
  text "DBG" at 7.4,4.3 h3
  text "CLK" at 8,1.7 h3
  text "JTAG" at -7.55,0.448 h3 r90
  text "UART0" at -5.512,0.35 h3 r90
  text "USER" at -31.525,0.303 h3
  text "RESET" at -22.825,0.303 h3
Bottom Overlay:
  drawing of 1109 lines, arcs and shapes, not listed
  text "VIN7" at 33.025,81 h1.5
  text "GND" at -30.5,80.936 h1.5
  text "VIN5" at 22.95,79.191 h1.5
  text "PB3" at -26.226,78.976 h1.5
  text "RX/PB7" at -19.221,78.967 h1.5
  text "PB11" at -32.756,77.127 h1.5 r45
  text "VIN4" at 22.95,76.476 h1.5
  text "PB7" at -26.222,76.444 h1.5
  text "TX/PB6" at -19.215,76.41 h1.5
  text "VIN6" at 34.521,75.425 h1.5 r315
  text "VIN3" at 22.95,74.091 h1.5
  text "PB10" at -33.053,74.053 h1.5
  text "PB6" at -26.21,73.926 h1.5
  text "PB8" at -20.901,73.944 h1.5
  text "GND" at 35.228,73.813 h1.5
  text "ADC" at 19.427,71.975 h1.5 r270
  text "PB9" at -32.975,71.499 h1.5
  text "PB8" at -26.21,71.399 h1.5
  text "VIN2" at 22.95,71.376 h1.5
  text "NC" at 34.297,71.285 h1.5
  text "PWM/PB15" at -17.331,71.222 h1.5
  text "GND" at -32.975,68.957 h1.5
  text "PB14" at -20.17,68.895 h1.5
  text "PB15" at -25.606,68.872 h1.5
  text "VIN1" at 22.95,68.876 h1.5
  text "NC" at 34.297,68.745 h1.5
  text "3V3" at -32.975,66.412 h1.5
  text "PB14" at -25.575,66.34 h1.5
  text "PWM/PB13" at -17.243,66.335 h1.5
  text "VIN0" at 22.95,66.291 h1.5
  text "GND" at 35.228,66.2 h1.5
  text "PB5" at -32.975,63.847 h1.5
  text "RST_ALL" at 28.225,63.859 h1.5
  text "PB13" at -25.603,63.823 h1.5
  text "МИКРОКОНТРОЛЛЕР BE-U1000 / ОТЛАДОЧНАЯ ПЛАТА BASE / РАЗРАБОТАНО В РОССИИ" at 11.395,63.71 h2
  text "PWM/PB12" at -17.156,63.701 h1.5
  text "PC15" at 35.36,63.669 h1.5
  text "VIN" at 23.318,61.3 h1.5
  text "PB12" at -25.599,61.291 h1.5
  text "PB2" at -20.726,61.286 h1.5
  text "PB4" at -32.975,61.183 h1.5
  text "PC14" at 35.392,61.131 h1.5
  text "PB2" at -26.222,58.769 h1.5
  text "GND" at 22.95,58.768 h1.5
  text "GND" at -32.975,58.736 h1.5
  text "PC13" at 35.364,58.588 h1.5
  text "PA13" at -20.1,57.247 h1.5
  text "PB0" at -26.206,56.252 h1.5
  text "GND" at 22.95,56.222 h1.5
  text "PB1" at -32.975,56.151 h1.5
  text "GND" at 35.228,56.044 h1.5
  text "POWER" at 19.209,54.867 h1.5 r270
  text "PWM/PA12" at -17.182,54.751 h1.5
  text "5V" at 22.95,53.685 h1.5
  text "PC12" at 35.368,53.516 h1.5
  text "GND" at -32.941,52.052 h1.5
  text "PA13" at -25.525,52.067 h1.5
  text "PWM/CS/PA8" at -16.04,51.955 h1.5
  text "3V3" at 22.95,51.138 h1.5
  text "PC11" at 35.36,50.976 h1.5
  text "PWM/MOSI/ PA10" at -13.724,49.549 h1.5
  text "PA12" at -32.941,49.531 h1.5
  text "PA8" at -26.132,49.528 h1.5
  text "RST_U" at 22.86,48.559 h1.5
  text "PC10" at 35.383,48.433 h1.5
  text "PA15" at -32.941,46.991 h1.5
  text "PA10" at -25.505,46.989 h1.5
  text "MISO/PA11" at -17.032,46.993 h1.5
  text "IOREF" at 22.95,46.077 h1.5
  text "3V3" at 28.225,46.027 h1.5
  text "PC9" at 34.747,45.895 h1.5
  text "PA14" at -32.941,44.459 h1.5
  text "PA11" at -25.528,44.46 h1.5
  text "SCK/PA9" at -18.032,44.467 h1.5
  text "NC" at 22.95,43.54 h1.5
  text "PC8" at 28.225,43.507 h1.5
  text "PC7" at 34.745,43.355 h1.5
  text "PA9" at -26.128,41.927 h1.5
  text "GND" at -32.941,41.909 h1.5
  text "GND" at -20.429,41.893 h1.5
  text "GND" at 28.225,40.968 h1.5
  text "PC6" at 34.756,40.812 h1.5
  text "PA7" at -32.941,39.388 h1.5
  text "GND" at -25.754,39.377 h1.5
  text "AREF" at -20.033,39.392 h1.5
  text "BootModes: (XP1)" at 10.938,39.061 h3
  text "PC5" at 28.225,38.273 h1.5
  text "PC4" at 34.769,38.273 h1.5
  text "AREF" at -25.148,36.881 h1.5
  text "PA6" at -32.941,36.849 h1.5
  text "SDA/PA5" at -18.2,36.815 h1.5
  text "PC3" at 28.225,35.906 h1.5
  text "PC2" at 34.761,35.906 h1.5
  text "DBG" at -12.414,34.662 h2.54 r270
  text "M2" at -10.599,34.662 h2.5 r270
  text "M1" at -8.772,34.662 h2.5 r270
  text "M0" at -6.831,34.662 h2.5 r270
  text "DBG" at 3.54,34.562 h2.54 r270
  text "M2" at 5.355,34.562 h2.5 r270
  text "M1" at 7.182,34.562 h2.5 r270
  text "M0" at 9.123,34.562 h2.5 r270
  text "PA5" at -25.951,34.322 h1.5
  text "SCL/PA4" at -18.405,34.331 h1.5
  text "PA3" at -32.941,34.306 h1.5
  text "PC1" at 28.225,33.19 h1.5
  text "PC0" at 34.761,33.19 h1.5
  text "JTAG EXT" at -13.125,31.966 h2.54
  text "EFLASH" at 2.945,31.959 h2.54
  text "PA4" at -25.89,31.793 h1.5
  text "PA2" at -32.941,31.774 h1.5
  text "PA1" at -32.95,29.244 h1.5
  text "PA0" at -25.875,29.215 h1.5
  text "UART" at 2.932,27.607 h2.54
  text "PYTH UART" at -13.125,27.288 h2.54
  text "Ext 10-48V from XP8-24" at 14.273,23.665 h2.54 r270
  text "Ext 5V from XP8-18" at 16.873,23.5 h2.54 r270
  text "5V from any USB TYPE-C" at 19.544,23.5 h2.54 r270
  text "QSPI" at 2.879,23.209 h2.54
  text "MULTI" at -13.121,23.001 h2.54
  text "RX0" at -29.549,22.438 h1.5 r270
  text "TX0" at -26.923,22.438 h1.5 r270
  text "GND" at -32.286,22.174 h1.5 r270
  text "MULTI USB" at -13.121,18.763 h2.54
  text "USB" at 2.879,18.77 h2.54
  text "USB/UART" at -13.137,15.068 h2.54
  text "CLK (XP1)" at -25.899,14.358 h2.54
  text "M0" at 11.462,11.956 h3
  text "Ext CLKI" at -28.207,11.688 h2.54
  text "JTAG INT" at -13.13,10.59 h2.54
  text "M1" at 11.462,9.416 h3
  text "GND" at 35.217,8.493 h1.5 r270
  text "Int RC" at -28.257,7.546 h2.54
  text "M2" at 11.462,6.876 h3
  text "PYTH USB" at -13.133,6.458 h2.54
  text "QR" at 27.065,5.56 h4
  text "DBG" at 11.6,4.3 h3
  text "FACT RST" at -13.133,2.182 h2.54
  text "EVU-BA-2.5" at 31.267,1.727 h4 r270
  text "CLK" at 11.4,1.6 h3
Dimensions:
  lines w0.254: -34.873,27.305 35.104,27.305 ; -31.75,79.46 31.75,79.46 ; 0,0 0,82.5 ; 34.596,19.812 34.977,19.812 ; 37,-8.975 66.575,-8.975 66.575,-3.545 37,-3.545 37,-8.975
  text "ProjectName: EVU-BA-2.3" at 37.75,-5.559 h2.5
  text "TimeStamp: .ModifiedDate .ModifiedTime" at 37.75,-7.937 h2.5
Board Shape:
  the board outline again, w0.15

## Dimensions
-36.8,79.3 to 36.8,79.3 on Dimensions
36.8,79.3 to 36.8,3.2 on Dimensions
36.8,79.3 to 38.5,82.5 on Dimensions
38.5,82.5 to 38.5,0 on Dimensions
-40,81 to 40,1.5 on Dimensions
-31.75,79.46 to 0,82.5 on Dimensions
